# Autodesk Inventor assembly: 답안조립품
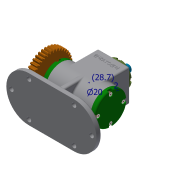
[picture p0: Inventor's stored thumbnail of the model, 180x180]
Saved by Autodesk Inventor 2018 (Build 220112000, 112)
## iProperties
Created: 2020-01
Part Number: 답안조립품
Document SubType Name: Assembly
Designer: Administrator
Author: Administrator
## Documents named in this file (18)
- C:\Users\expoc\Desktop\600104V1042\답안조립품.iam
- C:\Users\expoc\Desktop\600104V1042\본체.ipt
- C:\Users\expoc\Desktop\600104V1042\베어링 6203.ipt
- C:\Users\expoc\Desktop\600104V1042\편심축.ipt
- C:\Users\expoc\Desktop\600104V1042\앞커버.ipt
- C:\Users\expoc\Desktop\600104V1042\뒤커버.ipt
- C:\Users\expoc\Desktop\600104V1042\상부커버.ipt
- C:\Users\expoc\Desktop\600104V1042\볼트 M4.ipt
- C:\Users\expoc\Desktop\600104V1042\오일 실 17 30 5.ipt
- C:\Users\expoc\Desktop\600104V1042\Ű 4x4x12.ipt
- C:\Users\expoc\Desktop\600104V1042\스퍼기어.ipt
- C:\Users\expoc\Desktop\600104V1042\스프링와셔.ipt
- C:\Users\expoc\Desktop\600104V1042\평와셔.ipt
- C:\Users\expoc\Desktop\600104V1042\부시.ipt
- C:\Users\expoc\Desktop\600104V1042\멈춤링.ipt
- C:\Users\expoc\Desktop\600104V1042\슬라이더.ipt
- C:\Users\expoc\Desktop\600104V1042\스프링조립용 와셔.ipt
- C:\Users\expoc\Desktop\600104V1042\가변스프링.ipt
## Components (2 placed, 2 different names)
1. Ű 4x4x12:1
2. 가변스프링:1
